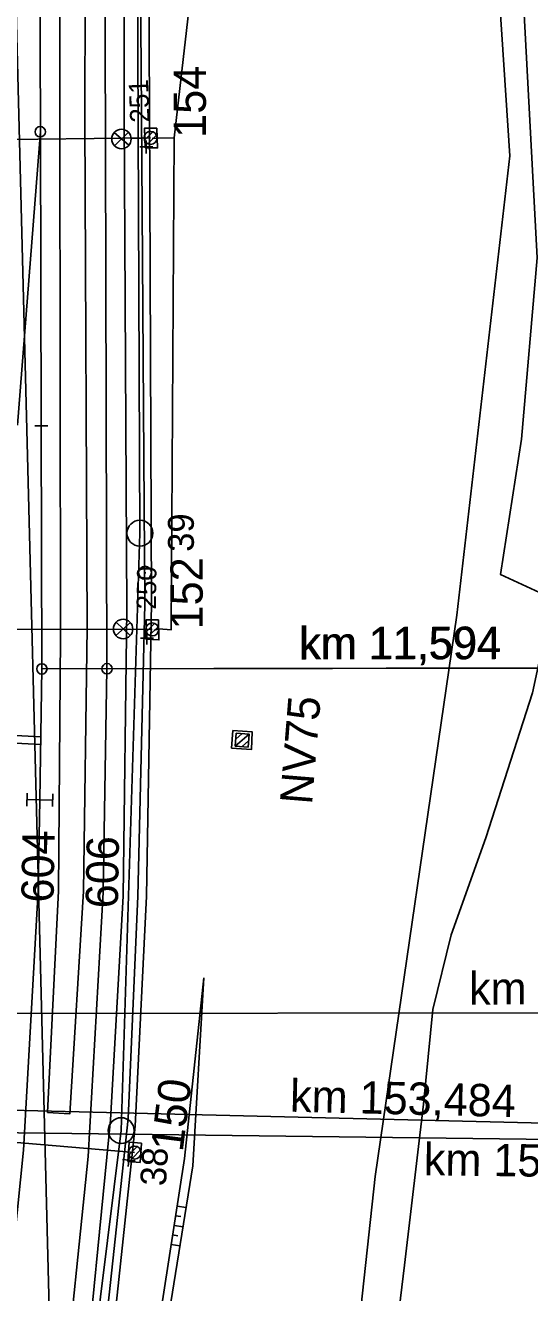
# Model space of a CAD drawing. Extents: x -598638 to -597933, y -1164002 to -1161904.
# Drawn here: x -598246.1 to -598207, y -1163336.1 to -1163238.1 of the extents above; entities that cross this region are included whole.
import ezdxf

# ---------------------------------------------------------------- set-up
doc = ezdxf.new("R2010")
doc.units = 0
for name, color, linetype in [('Vrstva 1', 7, 'Continuous'), ('Vrstva 11', 7, 'Continuous'), ('Vrstva 12', 7, 'Continuous'), ('Vrstva 2', 7, 'Continuous'), ('Vrstva 25', 7, 'Continuous'), ('Vrstva 26', 7, 'Continuous'), ('Vrstva 3', 7, 'Continuous'), ('Vrstva 31', 7, 'Continuous'), ('Vrstva 4', 7, 'Continuous'), ('Vrstva 43', 7, 'Continuous'), ('Vrstva 44', 7, 'Continuous'), ('Vrstva 48', 7, 'Continuous'), ('Vrstva 49', 7, 'Continuous'), ('Vrstva 5', 7, 'Continuous'), ('Vrstva 51', 7, 'Continuous'), ('Vrstva 63', 7, 'Continuous'), ('Vrstva 7', 7, 'Continuous')]:
    doc.layers.add(name, color=color, linetype=linetype)

msp = doc.modelspace()

# ---------------------------------------------------------------- linework, layer by layer
at = {"layer": 'Vrstva 1'}
for p, q in [((-598246.649, -1163269.02), (-598244.89, -1163246.328)), ((-598244.77, -1163287.888), (-598182.931, -1163287.746)), ((-598182.931, -1163287.804), (-598239.731, -1163287.87)), ((-598172.852, -1163314.447), (-598269.379, -1163314.559)), ((-598250.9, -1163321.936), (-598177.525, -1163323.686))]:
    msp.add_line(p, q, dxfattribs=at)
for points in [[(-598239.731, -1163287.87), (-598239.846, -1163247.571), (-598239.957, -1163214.082), (-598239.963, -1163212.175), (-598240, -1163201.726), (-598240.089, -1163175.503), (-598240.169, -1163146.755)], [(-598244.77, -1163287.888), (-598244.823, -1163269.091), (-598244.89, -1163246.328), (-598244.949, -1163226.279)], [(-598259.161, -1163402.069), (-598257.506, -1163395.492), (-598254.014, -1163379.874), (-598251.435, -1163366.348), (-598248.154, -1163344.226), (-598246.19, -1163325.096), (-598245.046, -1163305.011), (-598244.933, -1163298.014), (-598244.77, -1163287.888)], [(-598254.294, -1163403.303), (-598252.648, -1163396.738), (-598249.139, -1163381.102), (-598246.501, -1163367.254), (-598243.179, -1163344.93), (-598241.198, -1163325.59), (-598240.025, -1163305.166), (-598239.731, -1163287.87)]]:
    msp.add_lwpolyline(points, dxfattribs=at)
for centre in [(-598244.77, -1163287.888), (-598239.731, -1163287.87)]:
    msp.add_circle(centre, 0.4, dxfattribs=at)
at = {"layer": 'Vrstva 11'}
for p, q in [((-598236.821, -1163246.994), (-598236.175, -1163246.348)), ((-598236.561, -1163247.264), (-598235.906, -1163246.609)), ((-598236.691, -1163285.014), (-598236.045, -1163284.368)), ((-598236.431, -1163285.284), (-598235.776, -1163284.629)), ((-598229.805, -1163293.849), (-598228.738, -1163292.928)), ((-598229.766, -1163293.321), (-598229.266, -1163292.889)), ((-598229.28, -1163293.891), (-598228.773, -1163293.453)), ((-598238.051, -1163325.474), (-598237.405, -1163324.828)), ((-598237.791, -1163325.744), (-598237.136, -1163325.089))]:
    msp.add_line(p, q, dxfattribs=at)
for points in [[(-598249.46, -1163246.97), (-598236.36, -1163246.81)], [(-598251.59, -1163284.81), (-598236.23, -1163284.83)], [(-598229.732, -1163292.855), (-598228.735, -1163292.928), (-598228.808, -1163293.925), (-598229.805, -1163293.852), (-598229.732, -1163292.855)], [(-598254.91, -1163323.81), (-598237.59, -1163325.29)]]:
    msp.add_lwpolyline(points, dxfattribs=at)
msp.add_lwpolyline([(-598229.732, -1163292.855), (-598228.735, -1163292.928), (-598228.808, -1163293.925), (-598229.805, -1163293.852)], close=True, dxfattribs=at)
for centre in [(-598236.36, -1163246.81), (-598236.23, -1163284.83), (-598237.59, -1163325.29)]:
    msp.add_circle(centre, 0.5, dxfattribs=at)
at = {"layer": 'Vrstva 12'}
for points in [[(-598236.77, -1163247.58), (-598236.83, -1163246.07), (-598235.88, -1163246.06), (-598235.82, -1163247.58), (-598236.77, -1163247.58)], [(-598236.72, -1163285.59), (-598236.7, -1163284.09), (-598235.75, -1163284.09), (-598235.71, -1163285.64), (-598236.72, -1163285.59)], [(-598230.1, -1163294.01), (-598229.99, -1163292.65), (-598228.49, -1163292.76), (-598228.54, -1163294.11), (-598230.1, -1163294.01)], [(-598238.13, -1163325.99), (-598238.02, -1163324.48), (-598237.07, -1163324.57), (-598237.17, -1163326.06), (-598238.13, -1163325.99)]]:
    msp.add_lwpolyline(points, dxfattribs=at)
at = {"layer": 'Vrstva 2'}
msp.add_line((-598245.323, -1163269.092), (-598244.323, -1163269.09), dxfattribs=at)
for points in [[(-598244.823, -1163269.091), (-598244.89, -1163246.328), (-598244.949, -1163226.279)], [(-598246.649, -1163269.02), (-598244.89, -1163246.328)]]:
    msp.add_lwpolyline(points, dxfattribs=at)
msp.add_circle((-598244.892, -1163246.331), 0.4, dxfattribs=at)
at = {"layer": 'Vrstva 25'}
for p, q in [((-598239.181, -1163246.403), (-598238.034, -1163247.381)), ((-598239.157, -1163247.418), (-598238.072, -1163246.372)), ((-598237.859, -1163246.87), (-598236.36, -1163246.81)), ((-598239.055, -1163285.288), (-598237.916, -1163284.301)), ((-598239.026, -1163284.274), (-598237.932, -1163285.311)), ((-598237.73, -1163284.81), (-598236.23, -1163284.83))]:
    msp.add_line(p, q, dxfattribs=at)
for centre in [(-598238.612, -1163246.897), (-598238.484, -1163284.797)]:
    msp.add_circle(centre, 0.754, dxfattribs=at)
at = {"layer": 'Vrstva 26'}
for points in [[(-598234.532, -1163246.795), (-598231.747, -1163222.539), (-598232.401, -1163211.481), (-598233.074, -1163202.455), (-598231.426, -1163150.759)], [(-598234.532, -1163246.795), (-598235.775, -1163246.841), (-598236.227, -1163246.868)], [(-598234.532, -1163246.795), (-598234.759, -1163284.848), (-598235.726, -1163284.772), (-598236.082, -1163284.88)]]:
    msp.add_lwpolyline(points, dxfattribs=at)
at = {"layer": 'Vrstva 3'}
for p, q in [((-598245.944, -1163298.492), (-598245.922, -1163297.492)), ((-598245.933, -1163297.992), (-598243.933, -1163298.036)), ((-598243.944, -1163298.536), (-598243.922, -1163297.536))]:
    msp.add_line(p, q, dxfattribs=at)
at = {"layer": 'Vrstva 31'}
msp.add_lwpolyline([(-598207.807, -1163230.178), (-598207.737, -1163231.91), (-598206.446, -1163256.076), (-598207.647, -1163270.113), (-598209.267, -1163280.588), (-598205.591, -1163282.28), (-598205.96, -1163285.899), (-598206.803, -1163289.722), (-598210.416, -1163300.959), (-598213.085, -1163308.46), (-598214.501, -1163314.219), (-598215.23, -1163321.556), (-598216.701, -1163334.011), (-598218.19, -1163346.355), (-598219.432, -1163356.097), (-598220.134, -1163364.145)], dxfattribs=at)
at = {"layer": 'Vrstva 4'}
for points in [[(-598321.684, -1163563.952), (-598314.649, -1163552.341), (-598302.065, -1163529.781), (-598292.77, -1163512.02), (-598281.731, -1163489.572), (-598274.163, -1163472.668), (-598266.066, -1163452.17), (-598258.953, -1163431.709), (-598252.674, -1163410.241), (-598246.46, -1163386.104), (-598243.144, -1163368.884), (-598239.955, -1163345.756), (-598237.56, -1163323.253), (-598236.679, -1163305.47), (-598236.283, -1163282.744), (-598236.431, -1163244.569), (-598236.596, -1163214.625), (-598236.873, -1163174.881), (-598236.229, -1163131.239), (-598234.781, -1163108.249), (-598234.285, -1163099.455), (-598231.787, -1163078.342)], [(-598283.36, -1163489.15), (-598275.736, -1163471.917), (-598267.551, -1163451.028), (-598260.793, -1163431.262), (-598254.345, -1163409.722), (-598248.47, -1163385.636), (-598245.045, -1163368.352), (-598241.712, -1163345.6), (-598239.462, -1163322.753), (-598238.478, -1163305.467), (-598238.203, -1163283.28), (-598238.406, -1163245.16), (-598238.376, -1163215.168), (-598238.53, -1163175.26), (-598238.394, -1163131.328), (-598237.202, -1163108.683), (-598236.122, -1163097.625), (-598233.737, -1163078.205)]]:
    msp.add_lwpolyline(points, dxfattribs=at)
at = {"layer": 'Vrstva 43'}
for centre in [(-598237.183, -1163277.386), (-598238.629, -1163323.594)]:
    msp.add_circle(centre, 1, dxfattribs=at)
at = {"layer": 'Vrstva 44'}
msp.add_lwpolyline([(-598286.823, -1163498.793), (-598268.977, -1163457.491), (-598254.684, -1163414.899), (-598244.494, -1163370.7), (-598238.629, -1163323.594), (-598237.183, -1163277.386), (-598237.387, -1163227.403), (-598237.546, -1163176.839), (-598237.218, -1163130.355), (-598233.358, -1163084.011), (-598224.142, -1163038.365), (-598215.269, -1163005.578), (-598224.817, -1163002.559)], dxfattribs=at)
at = {"layer": 'Vrstva 48'}
for p, q in [((-598233.608, -1163329.552), (-598234.304, -1163329.444)), ((-598234.004, -1163330.249), (-598234.419, -1163330.185)), ((-598234.238, -1163331.731), (-598234.649, -1163331.667)), ((-598233.846, -1163331.033), (-598234.534, -1163330.926)), ((-598234.083, -1163332.514), (-598234.764, -1163332.408))]:
    msp.add_line(p, q, dxfattribs=at)
at = {"layer": 'Vrstva 49'}
for points in [[(-598218.985, -1163327.148), (-598212.65, -1163283.715), (-598208.558, -1163248.195), (-598210.74, -1163214.935), (-598218.187, -1163174.338), (-598225.543, -1163145.969), (-598230.824, -1163123.355), (-598234.781, -1163108.249)], [(-598312.315, -1163561.929), (-598312.053, -1163560.13), (-598297.72, -1163533.783), (-598287.557, -1163512.375), (-598279.159, -1163492.971), (-598271.476, -1163473.929), (-598263.327, -1163452.767), (-598256.849, -1163432.711), (-598250.447, -1163410.888), (-598244.786, -1163386.292), (-598240.759, -1163366.985), (-598236.936, -1163346.431), (-598233.733, -1163325.755), (-598232.232, -1163311.779)], [(-598232.232, -1163311.779), (-598233.089, -1163326.313), (-598236.119, -1163345.209), (-598237.446, -1163358.355), (-598243.268, -1163388.291), (-598247.561, -1163407.939), (-598253.242, -1163428.023), (-598260.918, -1163451.594), (-598268.495, -1163470.375), (-598277.5, -1163493.166), (-598288.559, -1163518.332), (-598296.048, -1163535.039), (-598302.041, -1163547.928), (-598308.079, -1163558.087)], [(-598218.985, -1163327.148), (-598221.29, -1163348.513), (-598225.915, -1163376.811), (-598231.389, -1163411.005), (-598238.962, -1163445.678)]]:
    msp.add_lwpolyline(points, dxfattribs=at)
at = {"layer": 'Vrstva 5'}
msp.add_lwpolyline([(-598254.89, -1163323.671), (-598190.734, -1163324.471)], dxfattribs=at)
at = {"layer": 'Vrstva 51'}
for points in [[(-598282.309, -1163489.477), (-598274.667, -1163472.413), (-598266.77, -1163451.853), (-598259.621, -1163431.675), (-598253.513, -1163410.04), (-598247.112, -1163385.98), (-598243.846, -1163368.944), (-598240.561, -1163345.639), (-598238.081, -1163322.667), (-598237.343, -1163305.453), (-598236.795, -1163282.909), (-598237.051, -1163244.829), (-598237.298, -1163214.833), (-598237.439, -1163175.203), (-598237.167, -1163131.222), (-598235.767, -1163108.629), (-598234.985, -1163097.818), (-598232.528, -1163078.41)], [(-598244.328, -1163322.203), (-598243.474, -1163305.056), (-598243.331, -1163285.364), (-598243.383, -1163245.466), (-598243.363, -1163215.192), (-598243.435, -1163181.227), (-598242.42, -1163165.706)], [(-598244.328, -1163322.203), (-598242.61, -1163322.308), (-598241.546, -1163305.067), (-598241.263, -1163284.703), (-598241.447, -1163245.468), (-598241.365, -1163215.435), (-598241.552, -1163181.218), (-598241.599, -1163165.738), (-598242.42, -1163165.706)]]:
    msp.add_lwpolyline(points, dxfattribs=at)
at = {"layer": 'Vrstva 63'}
msp.add_line((-598243.435, -1163367.735), (-598248.331, -1163175.227), dxfattribs=at)
at = {"layer": 'Vrstva 7'}
for p, q in [((-598237.191, -1163247.506), (-598236.191, -1163247.506)), ((-598236.691, -1163247.006), (-598236.691, -1163248.006)), ((-598236.836, -1163280.447), (-598236.736, -1163280.447)), ((-598237.141, -1163285.507), (-598236.141, -1163285.507)), ((-598236.641, -1163285.007), (-598236.641, -1163286.007)), ((-598248.613, -1163293.544), (-598244.864, -1163293.725)), ((-598248.565, -1163292.946), (-598244.854, -1163293.124)), ((-598237.544, -1163325.933), (-598238.538, -1163325.831)), ((-598237.99, -1163325.385), (-598238.092, -1163326.379))]:
    msp.add_line(p, q, dxfattribs=at)
msp.add_circle((-598236.786, -1163280.447), 0.5, dxfattribs=at)

# ---------------------------------------------------------------- texts
at = {"layer": 'Vrstva 1'}
for s, rotation, p in [('km 11,594', 0.07016, (-598224.877, -1163287.156)), ('km 11,594', 0.12708, (-598224.815, -1163287.14)), ('604', 89.07655, (-598243.868, -1163305.969)), ('606', 89.02617, (-598238.891, -1163306.416)), ('km 0,741', 0.07016, (-598211.71, -1163313.843)), ('km 153,484', 358.62978, (-598225.585, -1163322.132))]:
    msp.add_text(s, height=2.5, rotation=rotation, dxfattribs=at).set_placement(p)
at = {"layer": 'Vrstva 11'}
for s, rotation, p in [('154', 90, (-598232.073, -1163246.81)), ('152', 90, (-598232.322, -1163284.83)), ('NV75', 85.37071, (-598223.863, -1163298.422)), ('150', 82.90425, (-598233.871, -1163325.29))]:
    msp.add_text(s, height=2.5, rotation=rotation, dxfattribs=at).set_placement(p)
at = {"layer": 'Vrstva 25'}
for s, rotation, p in [('251', 92.27537, (-598236.431, -1163245.594)), ('250', 89.23612, (-598235.944, -1163283.293))]:
    msp.add_text(s, height=1.5, rotation=rotation, dxfattribs=at).set_placement(p)
at = {"layer": 'Vrstva 43'}
for s, rotation, p in [('39', 90.1635, (-598233.005, -1163278.827)), ('38', 86.71297, (-598235.171, -1163327.919))]:
    msp.add_text(s, height=2, rotation=rotation, dxfattribs=at).set_placement(p)
at = {"layer": 'Vrstva 5'}
msp.add_text('km 153,483', height=2.5, rotation=359.28552, dxfattribs=at).set_placement((-598215.221, -1163327.044))

doc.saveas('drawing.dxf')
